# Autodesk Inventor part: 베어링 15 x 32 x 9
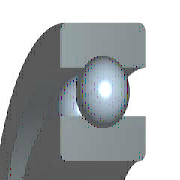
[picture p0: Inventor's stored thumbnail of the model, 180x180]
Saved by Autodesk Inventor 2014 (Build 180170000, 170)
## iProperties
IsCustomPart: 0
Created: 2012-02
Part Number: 베어링 15 x 32 x 9
Material: 강철, 연강
Description: 깊은 그루브 볼 베어링
Document SubType Name: Modeling
Standard: KS B 2023
Designer: mduedu
Standards Organization: KS
Language: ko-KR
Size Designation: 6002 - 15 x 32 x 9
Categories: <MemberInstance><Categories><Category DisplayName="샤프트 부품" InternalName="7f7aeb1f-a693-4053-b835-cee3144e0d98" Mnemonic="SHFT"><Category DisplayName="베어링" Inter
Density: 1 g/cm^3
Appearance: 강철
Author: mduedu
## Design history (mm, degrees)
sketch "스케치" dims "d0" = 4.42 (= -0.26 x WD + 0.26 x BD)
  geometry: L1 (2.29, 11.75)-(6.71, 11.75); L2 (4.5, 11.75)-(4.5, 9.54); L3 (4.5, 11.75)-(4.5, 13.96); L4 (2.858, 10.271)-(0, 10.271); L5 (0, 7.5)-(9, 7.5); L6 (2.858, 13.229)-(0, 13.229); L7 (0, 16)-(9, 16); L8 (9, 7.5)-(9, 10.271); L9 (6.142, 10.271)-(9, 10.271); L10 (6.142, 13.229)-(9, 13.229); L11 (9, 16)-(9, 13.229); L12 (-1.4, 0)-(8.4, 0) reference; L13 (0, -0.3)-(0, 5.3) reference
  constraints: 22 end point, 4 point on line, 2 collinear, 2 perpendicular, 2 symmetric about line, 1 midpoint, 1 parallel, 14 other
  dimensions: "d9" = 15 diameter of L5 L12 (= WD); "d11" = 32 diameter of L7 L12 (= BD); "d12" = 9 distance between parallel lines of L8 L13 (= KB); "d13" = 20.542 diameter of L9 L12 (= 0.326 x BD + 0.674 x WD)
revolve "본체" stored, may be unused: angle "d6" = 90 deg
revolve "볼" stored, may be unused: angle "d7" = 90 deg
pattern_circular "IDS_ARRAYBALL[SIMPL:T]" dims angle "d3" = 360 deg
body "Solid1"
fillet "모깎기1" dims "d1" = 0.3 (= KRS)
other parameters: "WD" = 15 [user parameter; used in 5 equation terms], "BD" = 32 [user parameter; used in 5 equation terms], "KB" = 9 [user parameter; used in 1 equation term], "KRS" = 0.3 [user parameter; used in 1 equation term], "d4" = 0, "d5" = 0, "d8" = 0, "d14" = 0, "d15" = 0, "BBA" = 0 [user parameter], "BC0" = 2850000 [user parameter], "BC" = 5590000 [user parameter], "BR" = 16 (= 0.5 x BD) [user parameter], "WR" = 7.5 (= 0.5 x WD) [user parameter]
